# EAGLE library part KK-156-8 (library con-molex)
KK 156 HEADER Source: http://www.molex.com/pdm_docs/sd/026604100_sd.pdf
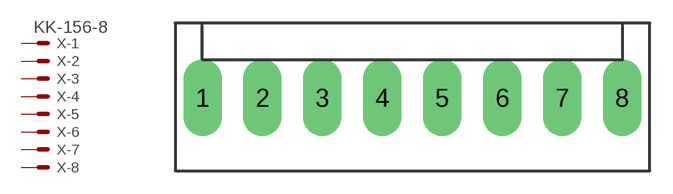
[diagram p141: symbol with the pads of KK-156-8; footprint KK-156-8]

Designator prefix X; gates -1=MV -2=M -3=M -4=M -5=M -6=M -7=M -8=M

## KK-156-8 (OC_FARNELL: unknown; OC_NEWARK: unknown)  [KK-156-8]
1  -1:S  pas
2  -2:S  pas
3  -3:S  pas
4  -4:S  pas
5  -5:S  pas
6  -6:S  pas
7  -7:S  pas
8  -8:S  pas

## Footprint KK-156-8 (pad centres in mm)
KK 156 HEADER Source: http://www.molex.com/pdm_docs/sd/026604100_sd.pdf
drill 1.7 pad 2.184 long: 1 -13.86,0; 2 -9.9,0; 3 -5.94,0; 4 -1.98,0; 5 1.98,0; 6 5.94,0; 7 9.9,0; 8 13.86,0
